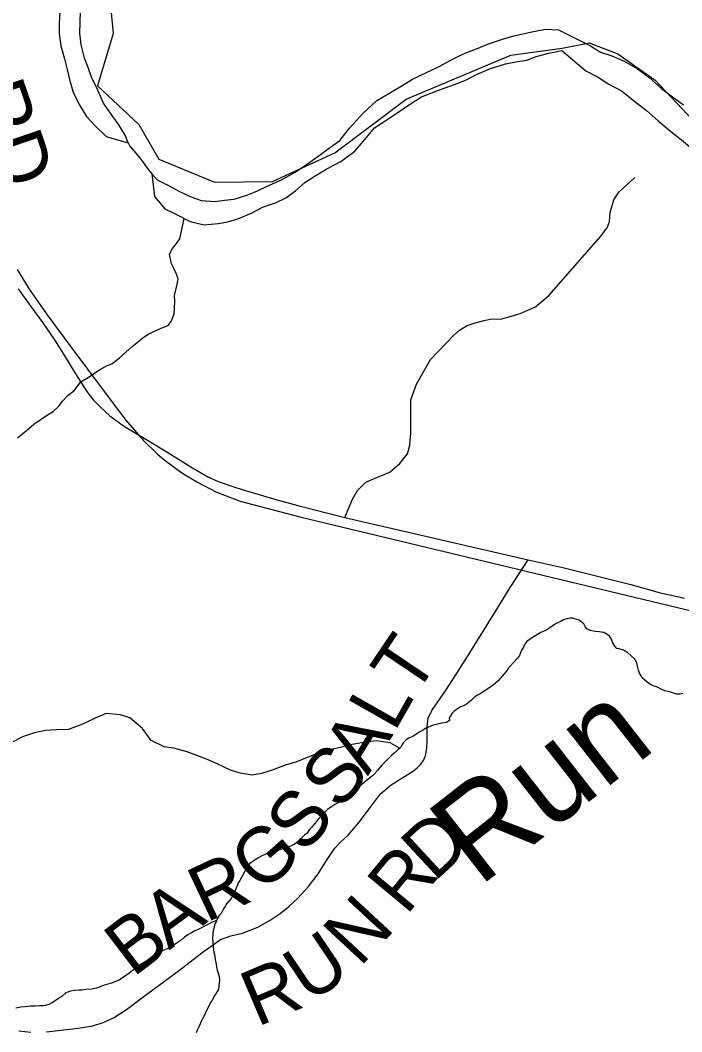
# Model space of a CAD drawing. Extents: x 0 to 34, y 0 to 22.
# Drawn here: x 7.162 to 7.5, y 17.744 to 18.262 of the extents above; entities that cross this region are included whole.
import ezdxf

# ---------------------------------------------------------------- set-up
doc = ezdxf.new("R2010")
doc.units = 0
for name, color, linetype in [('GM_X_Corporation', 7, 'Continuous'), ('GM_X_County_Road', 7, 'Continuous'), ('GM_X_County_Road_Text', 7, 'Continuous'), ('GM_X_Major_River', 7, 'Continuous'), ('GM_X_Minor_River', 7, 'Continuous'), ('GM_X_Minor_River_Text', 7, 'Continuous'), ('GM_X_Rail_Line', 7, 'Continuous'), ('GM_X_Township', 7, 'Continuous'), ('GM_X_Township_Road', 7, 'Continuous'), ('GM_X_Township_Road_Text', 7, 'Continuous')]:
    doc.layers.add(name, color=color, linetype=linetype)

msp = doc.modelspace()

# ---------------------------------------------------------------- linework, layer by layer
at = {"layer": 'GM_X_Corporation'}
msp.add_lwpolyline([(7.20608, 18.29256), (7.20958, 18.25507), (7.20169, 18.22823), (7.22276, 18.20849), (7.23306, 18.19084), (7.26148, 18.17895), (7.29107, 18.17939), (7.323, 18.19404), (7.35952, 18.22154), (7.41302, 18.24399), (7.43939, 18.24759), (7.45306, 18.25033), (7.46774, 18.24469), (7.48694, 18.23113), (7.50614, 18.2108)], dxfattribs=at)
at = {"layer": 'GM_X_County_Road'}
msp.add_lwpolyline([(7.16103, 18.12435), (7.1676, 18.11531), (7.17366, 18.10706), (7.17964, 18.09836), (7.18517, 18.08956), (7.19031, 18.08085), (7.19614, 18.07191), (7.19951, 18.0675), (7.20312, 18.06384), (7.20794, 18.0595), (7.21544, 18.05395), (7.22727, 18.04691), (7.23623, 18.04148), (7.24939, 18.03325), (7.25807, 18.02813), (7.26331, 18.02585), (7.27133, 18.02315), (7.27616, 18.02162), (7.28489, 18.01903), (7.29281, 18.01666), (7.3041, 18.0135), (7.31942, 18.00955), (7.32818, 18.00738), (7.4219, 17.98569), (7.4404, 17.98158), (7.47443, 17.97319), (7.48889, 17.96906), (7.50192, 17.96619)], dxfattribs=at)
at = {"layer": 'GM_X_Major_River'}
for points in [[(7.18241, 18.26636), (7.18209, 18.26009), (7.18198, 18.25515), (7.18279, 18.24885), (7.18473, 18.24216), (7.18613, 18.23661), (7.18752, 18.23088), (7.1891, 18.22514), (7.19219, 18.2188), (7.19604, 18.21263), (7.20049, 18.20779), (7.20607, 18.20235), (7.21737, 18.19916)], [(7.21737, 18.19916), (7.21576, 18.2031), (7.21246, 18.2083), (7.20823, 18.21429), (7.20473, 18.21949), (7.20166, 18.2264), (7.19857, 18.23274), (7.19678, 18.23772), (7.19499, 18.24251), (7.19324, 18.24921), (7.19261, 18.25531), (7.19286, 18.26652)], [(7.22945, 18.18331), (7.23215, 18.18013), (7.23835, 18.17715), (7.24323, 18.17439), (7.24905, 18.17161), (7.2547, 18.16959), (7.26152, 18.16907), (7.26666, 18.16972), (7.27161, 18.17038), (7.27849, 18.17252), (7.28347, 18.17451), (7.28846, 18.17688), (7.29574, 18.18015), (7.30266, 18.18419), (7.30902, 18.18844), (7.31384, 18.19176), (7.32078, 18.19694), (7.3256, 18.20027), (7.33049, 18.20663), (7.33729, 18.2141), (7.34446, 18.2208), (7.35157, 18.22484), (7.35773, 18.2287), (7.36273, 18.23164), (7.36983, 18.23511), (7.37635, 18.23821), (7.38384, 18.24224), (7.38998, 18.24516), (7.39553, 18.24732), (7.40166, 18.24986), (7.40874, 18.25219), (7.41466, 18.25397), (7.42457, 18.25604), (7.43086, 18.25725), (7.4375, 18.25692)], [(7.4375, 18.25692), (7.45373, 18.24875), (7.45887, 18.24553), (7.46471, 18.24373), (7.4711, 18.24097), (7.47785, 18.23706), (7.48364, 18.23278), (7.49035, 18.22678), (7.49577, 18.2227), (7.50138, 18.21862)], [(7.22945, 18.18331), (7.23083, 18.1716), (7.23601, 18.16541), (7.24108, 18.16302), (7.24896, 18.15887), (7.25614, 18.1572), (7.26336, 18.15781), (7.26832, 18.15866), (7.27348, 18.16026), (7.28076, 18.16334), (7.28595, 18.16628), (7.29264, 18.16843), (7.29801, 18.17098), (7.30283, 18.17449), (7.30767, 18.17877), (7.31248, 18.1819), (7.31902, 18.18576), (7.32613, 18.18961), (7.33326, 18.19479), (7.33755, 18.19983), (7.34339, 18.20675), (7.35014, 18.21117), (7.36227, 18.21948), (7.36728, 18.22261), (7.37207, 18.2246), (7.37704, 18.2264), (7.38431, 18.22892), (7.38948, 18.23109), (7.39581, 18.2342), (7.40271, 18.2371), (7.41036, 18.2396), (7.41646, 18.24081), (7.42122, 18.24147), (7.426, 18.24327), (7.4325, 18.24504), (7.43917, 18.24642)], [(7.43917, 18.24642), (7.45133, 18.23599), (7.45743, 18.23284), (7.46313, 18.2291), (7.46969, 18.22577), (7.47623, 18.22053), (7.48239, 18.21568), (7.48817, 18.21065), (7.4947, 18.20503), (7.50124, 18.19998), (7.50608, 18.19572), (7.51094, 18.19184), (7.5171, 18.18699), (7.52214, 18.18292), (7.52847, 18.17654), (7.53479, 18.17036), (7.54151, 18.16493), (7.54829, 18.16254), (7.55453, 18.16225), (7.56097, 18.16235), (7.56704, 18.16263)], [(7.21737, 18.19916), (7.2181, 18.19735), (7.22329, 18.19153), (7.22771, 18.18536), (7.22945, 18.18331)]]:
    msp.add_lwpolyline(points, dxfattribs=at)
at = {"layer": 'GM_X_Minor_River'}
for points in [[(7.16071, 18.04809), (7.1634, 18.05032), (7.16629, 18.05274), (7.16899, 18.05516), (7.17225, 18.05739), (7.17609, 18.05998), (7.17897, 18.06164), (7.18167, 18.06425), (7.1838, 18.06688), (7.18671, 18.07006), (7.18978, 18.07247), (7.19309, 18.07679), (7.19692, 18.079), (7.1998, 18.08104), (7.20268, 18.08289), (7.20651, 18.08511), (7.20899, 18.08601), (7.21284, 18.08918), (7.21939, 18.09495), (7.22189, 18.097), (7.22478, 18.09942), (7.22747, 18.10128), (7.23015, 18.10237), (7.23263, 18.10366), (7.23512, 18.10456), (7.23779, 18.10566), (7.23954, 18.1081), (7.24093, 18.11168), (7.24098, 18.11434), (7.24124, 18.11795), (7.2411, 18.12099), (7.24172, 18.12383), (7.24235, 18.12686), (7.24296, 18.12932), (7.24206, 18.13199), (7.24078, 18.13448), (7.2395, 18.13717), (7.23845, 18.14212), (7.24002, 18.14514), (7.24196, 18.14757), (7.24372, 18.15001), (7.24601, 18.16042)], [(7.50109, 17.91734), (7.49937, 17.91701), (7.49786, 17.91705), (7.49541, 17.91787), (7.49333, 17.91831), (7.49182, 17.91872), (7.49069, 17.91913), (7.48807, 17.92053), (7.48638, 17.92114), (7.48487, 17.92175), (7.483, 17.92294), (7.48151, 17.92412), (7.48021, 17.92529), (7.47967, 17.92644), (7.47895, 17.92779), (7.47842, 17.92932), (7.47807, 17.93066), (7.47773, 17.93218), (7.47738, 17.93333), (7.47647, 17.93487), (7.47443, 17.93682), (7.47295, 17.93819), (7.4707, 17.93958), (7.46844, 17.9402), (7.46731, 17.94042), (7.4662, 17.94159), (7.46511, 17.94352), (7.46457, 17.94505), (7.46347, 17.94659), (7.46236, 17.94757), (7.46068, 17.94856), (7.45935, 17.94879), (7.45821, 17.94882), (7.45613, 17.94906), (7.45367, 17.94951), (7.45199, 17.9505), (7.45107, 17.95166), (7.45034, 17.95301), (7.44904, 17.95399), (7.44792, 17.95478), (7.44566, 17.9556), (7.44453, 17.95582), (7.4432, 17.95585), (7.44167, 17.95551), (7.43995, 17.95499), (7.43822, 17.95408), (7.43668, 17.95337), (7.43533, 17.95264), (7.43301, 17.951), (7.43146, 17.9499), (7.42839, 17.94846), (7.42415, 17.94592), (7.42241, 17.94482), (7.42125, 17.9439), (7.42026, 17.9426), (7.41947, 17.94111), (7.41847, 17.93942), (7.41746, 17.93679), (7.41647, 17.93549), (7.41432, 17.93308), (7.41159, 17.92993), (7.4106, 17.92863), (7.40649, 17.9238), (7.40377, 17.92141), (7.3974, 17.91721), (7.39605, 17.91649), (7.3947, 17.91557), (7.39295, 17.91391), (7.39023, 17.91171), (7.38888, 17.91098), (7.38735, 17.91045), (7.38619, 17.90973), (7.38426, 17.90845), (7.38309, 17.90734), (7.38211, 17.90585), (7.38151, 17.90473), (7.38167, 17.90358), (7.38012, 17.90249), (7.37783, 17.90217), (7.37325, 17.90115), (7.36941, 17.89935), (7.36786, 17.89844), (7.36613, 17.89754), (7.36285, 17.89535), (7.36093, 17.89445), (7.35957, 17.89354), (7.35821, 17.89225), (7.35723, 17.89094), (7.35663, 17.88963), (7.35507, 17.88834), (7.35333, 17.88687), (7.35197, 17.88558), (7.35021, 17.88373)], [(7.35571, 17.88887), (7.35617, 17.88939), (7.35129, 17.89214), (7.34409, 17.89304), (7.33876, 17.89239), (7.3319, 17.89119), (7.32713, 17.88995), (7.3214, 17.88873), (7.31472, 17.88677), (7.30802, 17.88424), (7.30304, 17.88224), (7.29769, 17.88064), (7.29099, 17.87811), (7.28544, 17.87631), (7.28068, 17.87545), (7.27462, 17.87652), (7.26972, 17.87814), (7.26257, 17.88151), (7.2573, 17.8837), (7.2524, 17.88551), (7.2475, 17.88751), (7.2407, 17.88935), (7.23578, 17.89002), (7.22901, 17.89319), (7.22458, 17.89936), (7.21823, 17.90481), (7.21333, 17.90643), (7.20613, 17.90714), (7.20038, 17.90478), (7.19482, 17.90203), (7.18677, 17.89896), (7.18069, 17.8987), (7.17499, 17.89843), (7.16946, 17.8972), (7.16334, 17.89523), (7.15796, 17.89248)], [(7.35021, 17.88373), (7.34846, 17.88207), (7.34709, 17.88059), (7.34611, 17.87947), (7.34493, 17.87799), (7.34337, 17.87613), (7.34221, 17.87521), (7.34085, 17.87411), (7.3391, 17.87264), (7.33697, 17.87099), (7.33561, 17.86988), (7.33445, 17.86877), (7.33251, 17.86731), (7.33096, 17.86602), (7.3296, 17.86492), (7.32785, 17.86345), (7.32592, 17.86198), (7.32303, 17.86054), (7.32148, 17.85944), (7.31936, 17.85798), (7.31663, 17.85539), (7.31566, 17.85428), (7.31448, 17.85298), (7.3137, 17.85186), (7.31272, 17.85075), (7.31115, 17.84871), (7.30998, 17.8476), (7.3088, 17.84592), (7.30744, 17.84482), (7.30627, 17.84371), (7.30471, 17.84205), (7.30335, 17.84094), (7.30219, 17.84002), (7.2995, 17.83877), (7.29816, 17.83823), (7.29663, 17.83789), (7.29529, 17.83755), (7.29318, 17.83666), (7.29184, 17.83612), (7.28859, 17.83545), (7.28744, 17.83491), (7.28609, 17.83438), (7.28475, 17.83365), (7.28359, 17.83311), (7.28224, 17.8322), (7.28069, 17.8311), (7.27954, 17.83037), (7.27816, 17.8287), (7.27437, 17.82159), (7.27359, 17.82047), (7.27317, 17.81916), (7.27156, 17.81541), (7.26996, 17.81241), (7.26781, 17.80981), (7.26702, 17.8087), (7.26623, 17.80739), (7.26483, 17.80477), (7.26385, 17.80366), (7.26286, 17.80197), (7.26225, 17.80047), (7.26146, 17.79916), (7.26123, 17.79765), (7.26081, 17.79615), (7.26057, 17.79426), (7.26051, 17.7916), (7.26067, 17.79046), (7.26063, 17.78913), (7.26078, 17.78742), (7.2611, 17.78495), (7.26145, 17.7838), (7.26176, 17.78113), (7.26227, 17.77885), (7.26243, 17.77751), (7.26276, 17.7758), (7.26347, 17.77369), (7.26381, 17.77216), (7.26397, 17.77102), (7.26392, 17.76894), (7.2637, 17.7678), (7.26346, 17.76591), (7.26168, 17.76292), (7.26009, 17.76012), (7.2593, 17.759), (7.2587, 17.75769), (7.2573, 17.75507), (7.25649, 17.75301), (7.25549, 17.75114), (7.25489, 17.74982), (7.25409, 17.74833), (7.25328, 17.74645), (7.25267, 17.74495), (7.25207, 17.74364)], [(7.2625, 17.80109), (7.25958, 17.79997), (7.25842, 17.79924), (7.25573, 17.79799), (7.25304, 17.79654), (7.2515, 17.79582), (7.24977, 17.79492), (7.24784, 17.79383), (7.2461, 17.79255), (7.24435, 17.79108), (7.24242, 17.7898), (7.24087, 17.7887), (7.23914, 17.78761), (7.23721, 17.78671), (7.23549, 17.786), (7.23414, 17.78527), (7.23298, 17.78454), (7.23144, 17.78364), (7.23009, 17.78272), (7.22835, 17.78163), (7.2268, 17.78053), (7.22352, 17.77853), (7.22159, 17.77725), (7.22042, 17.77615), (7.21849, 17.77468), (7.21694, 17.77358), (7.21404, 17.77157), (7.21269, 17.77066), (7.21039, 17.76977), (7.20923, 17.76923), (7.20579, 17.76818), (7.20368, 17.76748), (7.20234, 17.76694), (7.20119, 17.76659), (7.19871, 17.76609), (7.19585, 17.76579), (7.19337, 17.76547), (7.19205, 17.76551), (7.18976, 17.76538), (7.18786, 17.76505), (7.18536, 17.76416), (7.18361, 17.7625), (7.18149, 17.76104), (7.17859, 17.75922), (7.17667, 17.75813), (7.17494, 17.75761), (7.1738, 17.75745), (7.1719, 17.7575), (7.16981, 17.75736), (7.16734, 17.75724), (7.16448, 17.75693), (7.16239, 17.7568), (7.15991, 17.75629)]]:
    msp.add_lwpolyline(points, dxfattribs=at)
at = {"layer": 'GM_X_Rail_Line'}
msp.add_lwpolyline([(7.16061, 18.13435), (7.16666, 18.12431), (7.17586, 18.11106), (7.18743, 18.0955), (7.20509, 18.07183), (7.216, 18.05739), (7.22498, 18.04704), (7.23229, 18.03987), (7.23631, 18.03652), (7.24481, 18.03022), (7.25278, 18.02547), (7.26212, 18.02061), (7.27452, 18.01583), (7.30519, 18.00771), (7.53235, 17.9532)], dxfattribs=at)
at = {"layer": 'GM_X_Township'}
msp.add_lwpolyline([(7.20608, 18.29256), (7.20958, 18.25507), (7.20169, 18.22823), (7.22276, 18.20849), (7.23306, 18.19084), (7.26148, 18.17895), (7.29107, 18.17939), (7.323, 18.19404), (7.35952, 18.22154), (7.41302, 18.24399), (7.43939, 18.24759), (7.45306, 18.25033), (7.46774, 18.24469), (7.48694, 18.23113), (7.50614, 18.2108)], dxfattribs=at)
at = {"layer": 'GM_X_Township_Road'}
for points in [[(7.32818, 18.00738), (7.33203, 18.01684), (7.33456, 18.02116), (7.33888, 18.02548), (7.34481, 18.02808), (7.35117, 18.03056), (7.35628, 18.03503), (7.36021, 18.03997), (7.36147, 18.04441), (7.36194, 18.05071), (7.36194, 18.06008), (7.36194, 18.06764), (7.36482, 18.07557), (7.37203, 18.08818), (7.38392, 18.10079), (7.38682, 18.10328), (7.39076, 18.10562), (7.39473, 18.107), (7.39933, 18.10821), (7.40243, 18.10884), (7.4085, 18.10913), (7.41203, 18.11016), (7.41779, 18.11181), (7.42572, 18.11521), (7.43257, 18.12097), (7.45925, 18.15152), (7.46243, 18.15591), (7.46344, 18.15884), (7.46391, 18.16349), (7.46569, 18.17002), (7.46824, 18.17394), (7.47649, 18.1814)], [(7.17548, 17.74418), (7.19172, 17.74599), (7.19927, 17.74728), (7.20454, 17.74897), (7.20974, 17.75135), (7.21648, 17.75565), (7.22284, 17.76038), (7.24306, 17.77543), (7.25504, 17.78452), (7.26454, 17.79139), (7.26984, 17.79324), (7.27586, 17.79474), (7.28369, 17.79781), (7.2899, 17.80132), (7.29513, 17.8048), (7.29952, 17.80832), (7.30407, 17.81261), (7.30955, 17.81853), (7.31445, 17.82506), (7.31912, 17.83233), (7.32303, 17.83813), (7.32629, 17.84158), (7.32987, 17.84484), (7.33551, 17.85145), (7.34175, 17.85988), (7.34636, 17.866), (7.35184, 17.87058), (7.36278, 17.87738), (7.36498, 17.87904), (7.36686, 17.88095), (7.36833, 17.88311), (7.36934, 17.8854), (7.37009, 17.88935), (7.37021, 17.89311), (7.37032, 17.90042), (7.37084, 17.90477), (7.37268, 17.90868), (7.37965, 17.91872), (7.38485, 17.92684), (7.39215, 17.93812), (7.40616, 17.96094), (7.41265, 17.97154), (7.4219, 17.98569)], [(7.1614, 17.74474), (7.16748, 17.74396)]]:
    msp.add_lwpolyline(points, dxfattribs=at)

# ---------------------------------------------------------------- texts
at = {"layer": 'GM_X_County_Road_Text'}
msp.add_text('RD', height=0.028409, rotation=288.8938, dxfattribs=at).set_placement((7.13566, 18.22556))
at = {"layer": 'GM_X_Minor_River_Text'}
msp.add_text('Run', height=0.047353, rotation=38.0042, dxfattribs=at).set_placement((7.39671, 17.81788))
at = {"layer": 'GM_X_Township_Road_Text'}
for s, rotation, p in [('T', 55.9854, (7.36367, 17.91507)), ('L', 60.4327, (7.35349, 17.89708)), ('A', 58.5559, (7.33993, 17.87488)), ('S', 51.6251, (7.32588, 17.85677)), ('S', 50.8026, (7.30781, 17.83471)), ('G', 41.3258, (7.28548, 17.81451)), ('D', 42.8074, (7.37382, 17.82055)), ('R', 50.2454, (7.35957, 17.80332)), ('R', 25.2628, (7.25713, 17.79979)), ('A', 36.1712, (7.23818, 17.78577)), ('N', 47.1108, (7.33581, 17.77689)), ('B', 37.3742, (7.21976, 17.7717)), ('U', 33.937, (7.30975, 17.75839)), ('R', 23.0597, (7.2832, 17.74649))]:
    msp.add_text(s, height=0.02841, rotation=rotation, dxfattribs=at).set_placement(p)

doc.saveas('drawing.dxf')
